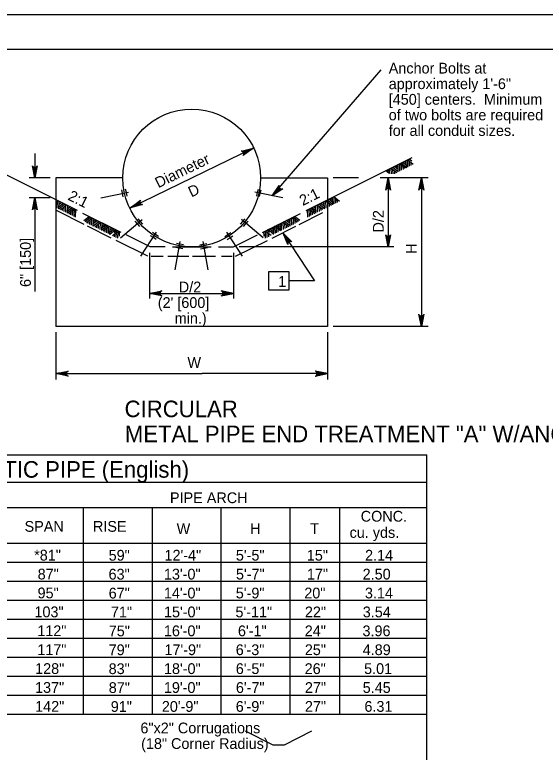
# Model space of a CAD drawing. Extents: x 1083.1 to 1117.1, y 675.4 to 741.4.
# Drawn here: x 1097.9 to 1105.58, y 730.66 to 741.35 of the extents above; entities that cross this region are included whole.
import ezdxf

# ---------------------------------------------------------------- set-up
doc = ezdxf.new("R2010")
doc.units = 0
doc.layers.add('Level 1', color=7, linetype='Continuous')

msp = doc.modelspace()

# ---------------------------------------------------------------- linework, layer by layer
at = {"layer": 'Level 1'}
for p, q in [((1101.358, 739.425), (1099.563, 738.55)), ((1098.187, 739.343), (1098.187, 738.988)), ((1101.193, 739.373), (1101.35, 739.422)), ((1101.204, 739.366), (1101.35, 739.422)), ((1101.212, 739.355), (1101.35, 739.422)), ((1101.216, 739.344), (1101.35, 739.422)), ((1101.216, 739.331), (1101.35, 739.422)), ((1102.118, 738.515), (1103.654, 739.283)), ((1103.571, 739.168), (1103.515, 739.213)), ((1103.57, 739.2), (1103.539, 739.226)), ((1103.572, 739.134), (1103.569, 739.241)), ((1103.671, 739.184), (1103.588, 739.25)), ((1103.593, 739.145), (1103.59, 739.248)), ((1103.648, 739.23), (1103.61, 739.261)), ((1103.617, 739.157), (1103.614, 739.229)), ((1098.803, 738.515), (1097.497, 739.168)), ((1098.164, 739.148), (1098.187, 738.988)), ((1098.175, 739.143), (1098.187, 738.988)), ((1098.211, 739.15), (1098.187, 738.988)), ((1098.201, 739.144), (1098.187, 738.988)), ((1098.187, 739.141), (1098.187, 738.988)), ((1103.327, 739.054), (1103.325, 739.118)), ((1103.43, 739.063), (1103.347, 739.13)), ((1103.353, 739.05), (1103.351, 739.126)), ((1103.453, 739.078), (1103.372, 739.142)), ((1103.378, 739.046), (1103.376, 739.106)), ((1103.452, 739.111), (1103.397, 739.155)), ((1103.45, 739.141), (1103.42, 739.166)), ((1103.453, 739.075), (1103.45, 739.181)), ((1103.554, 739.125), (1103.47, 739.191)), ((1103.477, 739.087), (1103.474, 739.188)), ((1103.572, 739.137), (1103.491, 739.202)), ((1103.502, 739.099), (1103.499, 739.168)), ((1103.527, 739.111), (1103.525, 739.147)), ((1103.64, 739.168), (1103.639, 739.21)), ((1103.316, 739.056), (1103.271, 739.091)), ((1103.326, 739.078), (1103.294, 739.103)), ((1103.327, 739.047), (1103.325, 739.048)), ((1103.403, 739.05), (1103.402, 739.086)), ((1098.409, 738.988), (1098.103, 738.988)), ((1098.492, 738.988), (1098.492, 736.835)), ((1099.462, 738.988), (1098.492, 738.988)), ((1101.459, 738.988), (1102.428, 738.988)), ((1102.428, 738.988), (1102.428, 736.835)), ((1102.876, 738.988), (1102.512, 738.988)), ((1103.888, 738.988), (1103.193, 738.988)), ((1103.282, 738.826), (1103.307, 738.988)), ((1103.292, 738.832), (1103.307, 738.988)), ((1103.307, 738.988), (1103.307, 738.302)), ((1103.307, 738.835), (1103.307, 738.988)), ((1103.318, 738.833), (1103.307, 738.988)), ((1103.329, 738.828), (1103.307, 738.988)), ((1103.763, 738.826), (1103.788, 738.988)), ((1103.774, 738.832), (1103.788, 738.988)), ((1103.788, 738.988), (1103.788, 737.787)), ((1103.788, 738.835), (1103.788, 738.988)), ((1103.799, 738.833), (1103.788, 738.988)), ((1103.81, 738.828), (1103.788, 738.988)), ((1099.141, 738.698), (1099.545, 738.784)), ((1099.458, 738.766), (1099.447, 738.815)), ((1099.513, 738.776), (1099.502, 738.827)), ((1101.78, 738.698), (1101.376, 738.784)), ((1101.415, 738.776), (1101.426, 738.826)), ((1101.453, 738.768), (1101.464, 738.818)), ((1101.726, 738.859), (1101.627, 738.731)), ((1101.73, 738.848), (1101.627, 738.731)), ((1101.736, 738.838), (1101.627, 738.731)), ((1101.749, 738.83), (1101.627, 738.731)), ((1101.76, 738.827), (1101.627, 738.731)), ((1098.409, 738.701), (1098.103, 738.701)), ((1098.162, 738.539), (1098.187, 738.701)), ((1098.172, 738.545), (1098.187, 738.701)), ((1098.187, 738.701), (1098.187, 737.343)), ((1098.187, 738.548), (1098.187, 738.701)), ((1098.198, 738.547), (1098.187, 738.701)), ((1098.209, 738.541), (1098.187, 738.701)), ((1099.469, 738.716), (1099.458, 738.766)), ((1099.524, 738.726), (1099.513, 738.776)), ((1101.403, 738.726), (1101.415, 738.776)), ((1101.442, 738.718), (1101.453, 738.768)), ((1102.503, 738.634), (1102.446, 738.679)), ((1102.502, 738.666), (1102.47, 738.691)), ((1102.503, 738.6), (1102.5, 738.707)), ((1102.603, 738.649), (1102.519, 738.716)), ((1102.525, 738.611), (1102.522, 738.714)), ((1102.548, 738.622), (1102.546, 738.695)), ((1098.492, 738.636), (1098.519, 738.657)), ((1098.512, 738.552), (1098.515, 738.654)), ((1098.536, 738.54), (1098.539, 738.647)), ((1098.536, 738.543), (1098.617, 738.608)), ((1098.537, 738.576), (1098.592, 738.62)), ((1098.539, 738.607), (1098.569, 738.632)), ((1098.559, 738.529), (1098.642, 738.595)), ((1098.611, 738.503), (1098.613, 738.572)), ((1098.636, 738.491), (1098.638, 738.592)), ((1098.661, 738.478), (1098.665, 738.584)), ((1099.708, 738.646), (1099.574, 738.556)), ((1099.708, 738.634), (1099.574, 738.556)), ((1099.712, 738.623), (1099.574, 738.556)), ((1099.721, 738.611), (1099.574, 738.556)), ((1099.731, 738.605), (1099.574, 738.556)), ((1102.259, 738.478), (1102.256, 738.584)), ((1102.362, 738.529), (1102.278, 738.595)), ((1102.285, 738.491), (1102.282, 738.592)), ((1102.384, 738.543), (1102.303, 738.608)), ((1102.31, 738.503), (1102.308, 738.572)), ((1102.383, 738.576), (1102.328, 738.62)), ((1102.382, 738.607), (1102.351, 738.632)), ((1102.384, 738.54), (1102.381, 738.647)), ((1102.485, 738.591), (1102.401, 738.657)), ((1102.408, 738.552), (1102.405, 738.654)), ((1102.503, 738.603), (1102.422, 738.668)), ((1102.433, 738.565), (1102.431, 738.634)), ((1102.458, 738.577), (1102.457, 738.613)), ((1102.571, 738.634), (1102.57, 738.676)), ((1098.901, 738.315), (1098.499, 738.516)), ((1098.586, 738.515), (1098.588, 738.552)), ((1098.662, 738.513), (1098.719, 738.557)), ((1098.662, 738.484), (1098.701, 738.516)), ((1098.663, 738.544), (1098.695, 738.569)), ((1098.678, 738.469), (1098.761, 738.536)), ((1098.701, 738.516), (1098.74, 738.547)), ((1098.709, 738.454), (1098.711, 738.496)), ((1098.732, 738.442), (1098.735, 738.514)), ((1098.756, 738.43), (1098.759, 738.534)), ((1098.777, 738.42), (1098.781, 738.526)), ((1099.436, 738.199), (1098.884, 738.475)), ((1101.485, 738.199), (1102.037, 738.475)), ((1102.019, 738.315), (1102.361, 738.486)), ((1102.143, 738.42), (1102.14, 738.526)), ((1102.243, 738.469), (1102.159, 738.536)), ((1102.165, 738.43), (1102.161, 738.534)), ((1102.219, 738.516), (1102.181, 738.547)), ((1102.188, 738.442), (1102.186, 738.514)), ((1102.258, 738.513), (1102.202, 738.557)), ((1102.211, 738.454), (1102.21, 738.496)), ((1102.259, 738.484), (1102.219, 738.516)), ((1102.257, 738.544), (1102.226, 738.569)), ((1102.334, 738.515), (1102.333, 738.552)), ((1098.896, 738.37), (1098.972, 738.431)), ((1098.914, 738.355), (1098.995, 738.419)), ((1098.933, 738.342), (1099.016, 738.408)), ((1098.959, 738.329), (1098.961, 738.364)), ((1098.985, 738.316), (1098.987, 738.385)), ((1099.009, 738.304), (1099.012, 738.405)), ((1099.033, 738.292), (1099.037, 738.398)), ((1099.033, 738.295), (1099.114, 738.359)), ((1099.034, 738.328), (1099.09, 738.372)), ((1099.036, 738.359), (1099.066, 738.383)), ((1099.426, 738.12), (1099.742, 738.385)), ((1099.674, 738.323), (1099.641, 738.362)), ((1099.718, 738.358), (1099.685, 738.397)), ((1099.751, 738.318), (1099.718, 738.358)), ((1101.168, 738.318), (1101.201, 738.358)), ((1101.495, 738.12), (1101.179, 738.385)), ((1101.201, 738.358), (1101.234, 738.397)), ((1101.245, 738.323), (1101.278, 738.362)), ((1101.887, 738.295), (1101.806, 738.359)), ((1101.886, 738.328), (1101.831, 738.372)), ((1101.885, 738.359), (1101.854, 738.383)), ((1101.887, 738.292), (1101.884, 738.398)), ((1101.988, 738.342), (1101.904, 738.408)), ((1101.911, 738.304), (1101.908, 738.405)), ((1102.006, 738.355), (1101.925, 738.419)), ((1101.936, 738.316), (1101.934, 738.385)), ((1102.025, 738.37), (1101.949, 738.431)), ((1101.961, 738.329), (1101.96, 738.364)), ((1099.295, 738.118), (1098.952, 738.29)), ((1099.056, 738.281), (1099.139, 738.347)), ((1099.084, 738.267), (1099.085, 738.303)), ((1099.108, 738.255), (1099.11, 738.324)), ((1099.133, 738.242), (1099.136, 738.344)), ((1099.159, 738.229), (1099.162, 738.336)), ((1099.159, 738.264), (1099.216, 738.309)), ((1099.159, 738.236), (1099.198, 738.267)), ((1099.16, 738.295), (1099.192, 738.321)), ((1099.175, 738.221), (1099.258, 738.288)), ((1099.198, 738.267), (1099.237, 738.298)), ((1099.229, 738.194), (1099.232, 738.266)), ((1099.253, 738.182), (1099.256, 738.285)), ((1099.274, 738.171), (1099.278, 738.278)), ((1099.275, 738.205), (1099.332, 738.251)), ((1099.276, 738.237), (1099.308, 738.263)), ((1099.707, 738.284), (1099.674, 738.323)), ((1101.212, 738.284), (1101.245, 738.323)), ((1101.645, 738.205), (1101.589, 738.251)), ((1101.644, 738.237), (1101.613, 738.263)), ((1101.626, 738.118), (1101.969, 738.29)), ((1101.646, 738.171), (1101.643, 738.278)), ((1101.746, 738.221), (1101.662, 738.288)), ((1101.668, 738.182), (1101.664, 738.285)), ((1101.722, 738.267), (1101.684, 738.298)), ((1101.691, 738.194), (1101.689, 738.266)), ((1101.761, 738.264), (1101.705, 738.309)), ((1101.762, 738.236), (1101.722, 738.267)), ((1101.76, 738.295), (1101.729, 738.321)), ((1101.762, 738.229), (1101.759, 738.336)), ((1101.865, 738.281), (1101.781, 738.347)), ((1101.788, 738.242), (1101.785, 738.344)), ((1101.813, 738.255), (1101.811, 738.324)), ((1101.837, 738.267), (1101.836, 738.303)), ((1103.307, 738.302), (1103.307, 737.988)), ((1099.207, 738.205), (1099.208, 738.247)), ((1099.274, 738.175), (1099.355, 738.239)), ((1099.312, 738.153), (1099.395, 738.219)), ((1099.335, 738.199), (1099.374, 738.23)), ((1099.343, 738.137), (1099.345, 738.179)), ((1099.366, 738.125), (1099.369, 738.198)), ((1099.39, 738.114), (1099.393, 738.217)), ((1099.413, 738.143), (1099.415, 738.21)), ((1099.856, 737.988), (1099.509, 738.162)), ((1099.725, 737.855), (1099.95, 738.202)), ((1099.904, 738.123), (1099.861, 738.151)), ((1099.934, 738.17), (1099.891, 738.198)), ((1099.977, 738.142), (1099.934, 738.17)), ((1100.942, 738.142), (1100.985, 738.17)), ((1101.196, 737.855), (1100.971, 738.202)), ((1100.985, 738.17), (1101.028, 738.198)), ((1101.015, 738.123), (1101.058, 738.151)), ((1101.064, 737.988), (1101.412, 738.162)), ((1101.508, 738.143), (1101.506, 738.21)), ((1101.609, 738.153), (1101.525, 738.219)), ((1101.531, 738.114), (1101.527, 738.217)), ((1101.586, 738.199), (1101.547, 738.23)), ((1101.554, 738.125), (1101.552, 738.198)), ((1101.646, 738.175), (1101.565, 738.239)), ((1101.577, 738.137), (1101.576, 738.179)), ((1101.714, 738.205), (1101.713, 738.247)), ((1101.869, 738.062), (1101.784, 738.19)), ((1101.858, 738.052), (1101.784, 738.19)), ((1101.853, 738.041), (1101.784, 738.19)), ((1101.879, 738.067), (1101.784, 738.19)), ((1101.891, 738.069), (1101.784, 738.19)), ((1103.284, 738.149), (1103.307, 737.988)), ((1103.295, 738.143), (1103.307, 737.988)), ((1103.331, 738.151), (1103.307, 737.988)), ((1103.321, 738.144), (1103.307, 737.988)), ((1099.826, 737.853), (1099.364, 738.084)), ((1099.947, 738.096), (1099.904, 738.123)), ((1100.221, 737.659), (1100.293, 738.065)), ((1100.29, 738.029), (1100.24, 738.038)), ((1100.7, 737.659), (1100.628, 738.065)), ((1100.628, 738.029), (1100.679, 738.038)), ((1100.972, 738.096), (1101.015, 738.123)), ((1101.095, 737.853), (1101.557, 738.084)), ((1103.307, 738.142), (1103.307, 737.988)), ((1100.074, 737.988), (1099.856, 737.988)), ((1100.18, 737.988), (1100.741, 737.988)), ((1100.279, 737.972), (1100.228, 737.981)), ((1100.33, 737.963), (1100.279, 737.972)), ((1100.341, 738.021), (1100.29, 738.029)), ((1100.578, 738.021), (1100.628, 738.029)), ((1100.589, 737.963), (1100.639, 737.972)), ((1100.639, 737.972), (1100.69, 737.981)), ((1100.846, 737.988), (1101.064, 737.988)), ((1103.39, 737.988), (1101.148, 737.988)), ((1099.848, 737.905), (1099.848, 737.242)), ((1099.87, 737.853), (1100.044, 737.853)), ((1100.113, 737.853), (1100.419, 737.853)), ((1100.471, 737.853), (1100.803, 737.853)), ((1100.892, 737.853), (1101.045, 737.853)), ((1101.064, 737.905), (1101.064, 737.242)), ((1103.788, 737.787), (1103.788, 736.835)), ((1101.573, 737.627), (1101.573, 737.366)), ((1101.872, 737.627), (1101.573, 737.627)), ((1101.872, 737.366), (1101.872, 737.627)), ((1102.238, 737.496), (1101.872, 737.496)), ((1100.008, 737.338), (1099.848, 737.316)), ((1100.002, 737.327), (1099.848, 737.316)), ((1099.848, 737.316), (1101.064, 737.316)), ((1100.001, 737.316), (1099.848, 737.316)), ((1100.004, 737.301), (1099.848, 737.316)), ((1100.01, 737.291), (1099.848, 737.316)), ((1100.902, 737.291), (1101.064, 737.316)), ((1100.904, 737.338), (1101.064, 737.316)), ((1100.908, 737.301), (1101.064, 737.316)), ((1100.91, 737.327), (1101.064, 737.316)), ((1100.911, 737.316), (1101.064, 737.316)), ((1101.573, 737.366), (1101.872, 737.366)), ((1103.766, 736.995), (1103.788, 736.835)), ((1103.777, 736.99), (1103.788, 736.835)), ((1103.813, 736.997), (1103.788, 736.835)), ((1103.802, 736.991), (1103.788, 736.835)), ((1103.788, 736.988), (1103.788, 736.835)), ((1102.428, 736.835), (1098.492, 736.835)), ((1103.888, 736.835), (1102.512, 736.835)), ((1098.492, 736.752), (1098.492, 736.068)), ((1102.428, 736.752), (1102.428, 736.068)), ((1098.652, 736.174), (1098.492, 736.152)), ((1098.647, 736.163), (1098.492, 736.152)), ((1098.492, 736.152), (1100.61, 736.152)), ((1098.645, 736.152), (1098.492, 736.152)), ((1098.648, 736.137), (1098.492, 736.152)), ((1098.654, 736.127), (1098.492, 736.152)), ((1102.428, 736.152), (1100.61, 736.152)), ((1102.266, 736.127), (1102.428, 736.152)), ((1102.268, 736.174), (1102.428, 736.152)), ((1102.272, 736.137), (1102.428, 736.152)), ((1102.274, 736.163), (1102.428, 736.152)), ((1102.275, 736.152), (1102.428, 736.152)), ((1086.66, 734.976), (1103.868, 734.976)), ((1103.868, 720.144), (1103.868, 734.976)), ((1103.868, 734.576), (1086.654, 734.576)), ((1103.868, 734.205), (1086.654, 734.205)), ((1098.89, 731.212), (1098.89, 734.205)), ((1099.89, 733.692), (1099.89, 734.205)), ((1099.89, 731.212), (1099.89, 734.205)), ((1100.889, 733.692), (1100.889, 734.205)), ((1100.889, 731.212), (1100.889, 734.205)), ((1101.889, 733.692), (1101.889, 734.205)), ((1101.889, 731.213), (1101.889, 734.205)), ((1102.605, 731.213), (1102.605, 734.205)), ((1103.868, 733.692), (1086.654, 733.692)), ((1103.868, 733.692), (1086.689, 733.692)), ((1103.868, 733.416), (1086.654, 733.416)), ((1103.868, 733.141), (1086.654, 733.141)), ((1103.868, 732.865), (1086.654, 732.865)), ((1103.868, 732.59), (1086.654, 732.59)), ((1103.868, 732.315), (1086.654, 732.315)), ((1103.868, 732.039), (1086.654, 732.039)), ((1103.868, 731.764), (1086.654, 731.764)), ((1103.868, 731.489), (1086.654, 731.489)), ((1103.868, 731.213), (1086.654, 731.213)), ((1097.894, 731.214), (1103.868, 731.213)), ((1101.235, 730.974), (1101.634, 730.773)), ((1101.805, 730.774), (1102.203, 730.975)), ((1101.634, 730.773), (1101.805, 730.774))]:
    msp.add_line(p, q, dxfattribs=at)
for points in [[(1083.126, 719.354), (1117.126, 719.354), (1117.126, 741.354), (1083.126, 741.354)], [(1085.126, 740.854), (1116.626, 740.854), (1116.626, 719.854), (1085.126, 719.854)]]:
    msp.add_lwpolyline(points, close=True, dxfattribs=at)
for points in [[(1101.627, 738.731), (1103.203, 740.558)], [(1101.175, 739.376), (1101.35, 739.422), (1101.206, 739.312)], [(1098.222, 739.165), (1098.187, 738.988), (1098.151, 739.165)], [(1103.271, 738.811), (1103.307, 738.988), (1103.342, 738.811)], [(1103.753, 738.811), (1103.788, 738.988), (1103.823, 738.811)], [(1101.778, 738.83), (1101.627, 738.731), (1101.729, 738.88)], [(1098.151, 738.524), (1098.187, 738.701), (1098.222, 738.524)], [(1099.749, 738.602), (1099.574, 738.556), (1099.718, 738.665)], [(1101.852, 738.023), (1101.784, 738.19), (1101.911, 738.062)], [(1101.784, 738.19), (1102.238, 737.496)], [(1103.342, 738.165), (1103.307, 737.988), (1103.271, 738.165)], [(1100.025, 737.28), (1099.848, 737.316), (1100.025, 737.351)], [(1100.887, 737.28), (1101.064, 737.316), (1100.887, 737.351)], [(1103.823, 737.012), (1103.788, 736.835), (1103.753, 737.012)], [(1098.669, 736.116), (1098.492, 736.152), (1098.669, 736.187)], [(1102.251, 736.116), (1102.428, 736.152), (1102.251, 736.187)]]:
    msp.add_lwpolyline(points, dxfattribs=at)
for centre, start, end in [((1101.178, 739.338), 318.0819, 93.908), ((1098.187, 739.179), 202.0878, 337.9139), ((1101.764, 738.865), 156.6853, 292.5114), ((1103.307, 738.797), 22.0878, 157.9139), ((1103.788, 738.797), 22.0878, 157.9139), ((1099.746, 738.64), 138.0819, 273.908), ((1098.187, 738.51), 22.0878, 157.9139), ((1103.307, 738.18), 202.0878, 337.9139), ((1101.89, 738.031), 55.7367, 191.5628), ((1100.039, 737.316), 112.0878, 247.9139), ((1100.873, 737.316), 292.0861, 67.9122), ((1103.788, 737.026), 202.0878, 337.9139), ((1098.684, 736.152), 112.0878, 247.9139), ((1102.237, 736.152), 292.0861, 67.9122)]:
    msp.add_arc(centre, 0.0382, start, end, dxfattribs=at)
msp.add_ellipse((1100.46, 738.988), major_axis=(0.999, 0), ratio=0.999895, dxfattribs=at)

# ---------------------------------------------------------------- texts
for s, height, p in [('Anchor Bolts at', 0.156, (1103.315, 740.502)), ('approximately 1\'-6"', 0.156, (1103.315, 740.276)), ('[450] centers.  Minimum', 0.156, (1103.315, 740.05)), ('of two bolts are required', 0.156, (1103.315, 739.824)), ('for all conduit sizes.', 0.156, (1103.315, 739.598)), ('1', 0.16, (1101.712, 737.408)), ('D/2', 0.156, (1100.273, 737.33)), ("(2' [600]", 0.156, (1099.968, 737.104)), ('min.)', 0.156, (1100.213, 736.878)), ('W', 0.156, (1100.398, 736.235)), ('CIRCULAR', 0.24, (1099.487, 735.521)), ('METAL PIPE END TREATMENT "A" W/ANCHOR BOLT OPTION', 0.24, (1099.491, 735.158)), ('CAST IN PLACE HW FOR CORRUGATED METAL PIPE & PLASTIC PIPE (English)', 0.24, (1088.367, 734.644)), ('PIPE ARCH', 0.156, (1100.145, 734.275)), ('CONC.', 0.156, (1102.909, 734.007)), ('SPAN', 0.156, (1098.038, 733.86)), ('RISE', 0.156, (1099.029, 733.86)), ('W', 0.156, (1100.242, 733.827)), ('H', 0.156, (1101.307, 733.827)), ('T', 0.156, (1102.176, 733.827)), ('cu. yds.', 0.156, (1102.748, 733.772)), ('*81"', 0.156, (1098.177, 733.443)), ('59"', 0.156, (1099.256, 733.441)), ('12\'-4"', 0.156, (1100.066, 733.442)), ('5\'-5"', 0.156, (1101.1, 733.442)), ('15"', 0.156, (1102.128, 733.442)), ('2.14', 0.156, (1102.972, 733.442)), ('87"', 0.156, (1098.228, 733.169)), ('63"', 0.156, (1099.255, 733.167)), ('13\'-0"', 0.156, (1100.057, 733.168)), ('5\'-7"', 0.156, (1101.101, 733.168)), ('17"', 0.156, (1102.129, 733.168)), ('2.50', 0.156, (1102.937, 733.168)), ('95"', 0.156, (1098.226, 732.895)), ('67"', 0.156, (1099.257, 732.893)), ('14\'-0"', 0.156, (1100.057, 732.894)), ('5\'-9"', 0.156, (1101.099, 732.894)), ('20"', 0.156, (1102.091, 732.894)), ('3.14', 0.156, (1102.97, 732.894)), ('103"', 0.156, (1098.181, 732.621)), ('71"', 0.156, (1099.289, 732.619)), ('15\'-0"', 0.156, (1100.058, 732.62)), ('5\'-11"', 0.156, (1101.094, 732.62)), ('22"', 0.156, (1102.1, 732.62)), ('3.54', 0.156, (1102.939, 732.62)), ('112"', 0.156, (1098.222, 732.347)), ('75"', 0.156, (1099.258, 732.345)), ('16\'-0"', 0.156, (1100.057, 732.346)), ('6\'-1"', 0.156, (1101.13, 732.346)), ('24"', 0.156, (1102.098, 732.346)), ('3.96', 0.156, (1102.935, 732.346)), ('117"', 0.156, (1098.222, 732.073)), ('79"', 0.156, (1099.257, 732.071)), ('17\'-9"', 0.156, (1100.065, 732.072)), ('6\'-3"', 0.156, (1101.098, 732.072)), ('25"', 0.156, (1102.099, 732.072)), ('4.89', 0.156, (1102.938, 732.072)), ('128"', 0.156, (1098.191, 731.799)), ('83"', 0.156, (1099.256, 731.797)), ('18\'-0"', 0.156, (1100.058, 731.798)), ('6\'-5"', 0.156, (1101.099, 731.798)), ('26"', 0.156, (1102.097, 731.798)), ('5.01', 0.156, (1102.958, 731.798)), ('137"', 0.156, (1098.19, 731.525)), ('87"', 0.156, (1099.258, 731.523)), ('19\'-0"', 0.156, (1100.057, 731.524)), ('6\'-7"', 0.156, (1101.1, 731.524)), ('27"', 0.156, (1102.1, 731.524)), ('5.45', 0.156, (1102.938, 731.524)), ('142"', 0.156, (1098.191, 731.251)), ('20\'-9"', 0.156, (1100.027, 731.25)), ('6\'-9"', 0.156, (1101.098, 731.25)), ('27"', 0.156, (1102.1, 731.25)), ('6.31', 0.156, (1102.963, 731.25)), ('91"', 0.156, (1099.287, 731.249)), ('6"x2" Corrugations', 0.156, (1099.717, 730.938)), ('(18" Corner Radius)', 0.156, (1099.727, 730.712))]:
    msp.add_text(s, height=height, dxfattribs=at).set_placement(p)
for s, rotation, p in [('Diameter', 25.9977, (1099.976, 738.838)), ('2:1', 333.4374, (1098.654, 738.679)), ('D', 25.9977, (1100.456, 738.705)), ('2:1', 26.5626, (1102.07, 738.58)), ('D/2', 90, (1103.242, 738.198)), ('6" [150]', 90, (1098.129, 737.408)), ('H', 90, (1103.721, 737.888))]:
    msp.add_text(s, height=0.156, rotation=rotation, dxfattribs=at).set_placement(p)

doc.saveas('drawing.dxf')
